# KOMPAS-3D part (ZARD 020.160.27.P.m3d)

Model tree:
1. Плоскость XY
2. Плоскость ZX
3. Плоскость ZY
4. Ось X
5. Ось Y
6. Ось Z
7. Начало координат
8. Булева операция:1
9. Булева операция:2
10. Булева операция:3
11. Булева операция:4
